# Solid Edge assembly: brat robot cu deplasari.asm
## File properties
Author: User
Template: Iso Metric Assembly.asm
Last saved by: User
Revision: 9
Application: Solid Edge
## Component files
sina.par
stalp.par
brat orizontal.par
gheara.par
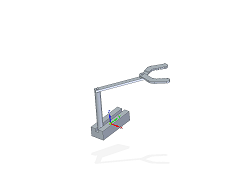
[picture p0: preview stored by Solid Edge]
